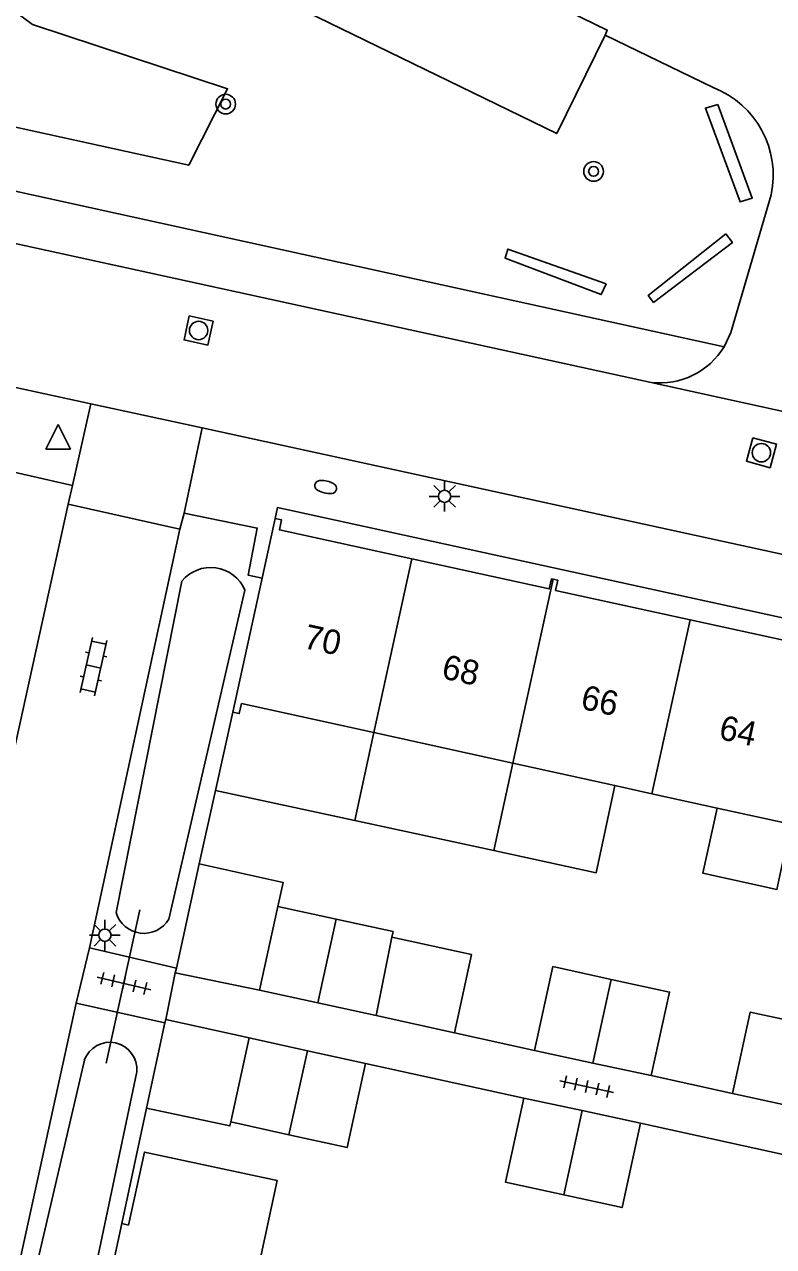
# Model space of a CAD drawing. Extents: x 130998 to 133001, y 398999 to 403002.
# Drawn here: x 131030.54 to 131061.09, y 399033.29 to 399083.14 of the extents above; entities that cross this region are included whole.
import ezdxf

# ---------------------------------------------------------------- set-up
doc = ezdxf.new("R2010")
doc.units = 0
for name, color, linetype in [('gg-afsc-erfafscheiding', 7, 'Continuous'), ('gg-afsc-muur', 7, 'Continuous'), ('gg-anno-huisnummerreeks BGT', 7, 'Continuous'), ('gg-bbg-bijgebouw', 7, 'Continuous'), ('gg-bbg-gedigitaliseerde bebouwing', 7, 'Continuous'), ('gg-bbg-gedigitaliseerde bijgebouw', 7, 'Continuous'), ('gg-bbg-hoofdgebouw', 7, 'Continuous'), ('gg-bbg-luifel en loopbrug', 7, 'Continuous'), ('gg-bbg-tussenscheiding', 7, 'Continuous'), ('gg-knt-verharding', 7, 'Continuous'), ('gg-knt-verharding nz', 7, 'Continuous'), ('gg-kntw-greppel-droge sloot', 7, 'Continuous'), ('gg-kwrk-duiker nz buis', 7, 'Continuous'), ('gt-grn-groengrens', 7, 'Continuous'), ('gt-grn-weggrens', 7, 'Continuous'), ('gt-symb-boom', 7, 'Continuous'), ('gt-symb-brandkraan', 7, 'Continuous'), ('gt-symb-klinker verharding', 7, 'Continuous'), ('gt-symb-lichtmast', 7, 'Continuous'), ('gt-symb-rioolschacht', 7, 'Continuous'), ('gt-symb-tegel verharding', 7, 'Continuous'), ('gt-symb-waterafsluiter', 7, 'Continuous')]:
    doc.layers.add(name, color=color, linetype=linetype)

# ---------------------------------------------------------------- blocks, each defined once
blk = doc.blocks.new('gt0-WAFSL')
at = {"layer": 'gt-symb-waterafsluiter'}
for p, q in [((-0.5, -0.333), (0, 0.667)), ((0, 0.667), (0.5, -0.333)), ((0.5, -0.333), (-0.5, -0.333))]:
    blk.add_line(p, q, dxfattribs=at)
blk = doc.blocks.new('gt0-RS')
at = {"layer": 'gt-symb-rioolschacht'}
blk.add_lwpolyline([(-0.5, -0.5), (0.5, -0.5), (0.5, 0.5), (-0.5, 0.5)], close=True, dxfattribs=at)
blk.add_circle((0, 0), 0.375, dxfattribs=at)
blk = doc.blocks.new('gt0-BR')
at = {"layer": 'gt-symb-brandkraan'}
for centre, radius, start, end in [((-0.244, 0), 0.206, 107.5669, 252.4331), ((0.599, -2.664), 3, 106.892, 107.5669), ((0, -0.691), 0.938, 73.108, 106.892), ((-0.599, -2.664), 3, 72.4331, 73.108), ((0.244, 0), 0.206, 287.567, 72.4331), ((0.599, 2.664), 3, 252.4331, 253.108), ((0, 0.691), 0.938, 253.108, 286.8921), ((-0.599, 2.664), 3, 286.8921, 287.567)]:
    blk.add_arc(centre, radius, start, end, dxfattribs=at)
blk = doc.blocks.new('gt0-LMAST')
at = {"layer": 'gt-symb-lichtmast'}
for p, q in [((-0.005, 0.246), (-0.005, 0.621)), ((-0.182, 0.173), (-0.447, 0.438)), ((0.172, 0.173), (0.437, 0.438)), ((-0.255, -0.004), (-0.63, -0.004)), ((-0.182, -0.181), (-0.447, -0.446)), ((-0.005, -0.254), (-0.005, -0.629)), ((0.437, -0.446), (0.172, -0.181)), ((0.245, -0.004), (0.62, -0.004))]:
    blk.add_line(p, q, dxfattribs=at)
blk.add_circle((-0.005, -0.004), 0.25, dxfattribs=at)
blk = doc.blocks.new('gt0-KL1')
at = {"layer": 'gt-symb-klinker verharding'}
for p, q in [((-1.15, 0.3), (1.15, 0.3)), ((-1, -0.3), (-1, 0.3)), ((-0.5, 0.3), (-0.5, 0.45)), ((0, -0.3), (0, 0.3)), ((0.5, 0.3), (0.5, 0.45)), ((1, -0.3), (1, 0.3)), ((-1.15, -0.3), (1.15, -0.3)), ((-0.5, -0.45), (-0.5, -0.3)), ((0.5, -0.45), (0.5, -0.3))]:
    blk.add_line(p, q, dxfattribs=at)
blk = doc.blocks.new('gt0-TEG1')
at = {"layer": 'gt-symb-tegel verharding'}
for p, q in [((-1.125, 0), (1.125, 0)), ((-0.9, -0.25), (-0.9, 0.25)), ((-0.45, -0.25), (-0.45, 0.25)), ((0, -0.25), (0, 0.25)), ((0.45, -0.25), (0.45, 0.25)), ((0.9, -0.25), (0.9, 0.25))]:
    blk.add_line(p, q, dxfattribs=at)
blk = doc.blocks.new('gt0-BOOM')
at = {"layer": 'gt-symb-boom'}
for radius in [0.4, 0.2]:
    blk.add_circle((0, 0), radius, dxfattribs=at)

msp = doc.modelspace()

# ---------------------------------------------------------------- linework, layer by layer
at = {"layer": 'gg-afsc-erfafscheiding'}
for p, q in [((131048.074, 399042.005), (131051.342, 399041.283)), ((131050.902, 399039.338), (131044.456, 399040.753)), ((131056.104, 399040.26), (131059.416, 399039.532)), ((131062.165, 399036.895), (131055.667, 399038.326))]:
    msp.add_line(p, q, dxfattribs=at)
at = {"layer": 'gg-afsc-muur'}
for p, q in [((131037.674, 399048.894), (131038.336, 399051.895)), ((131035.525, 399038.934), (131034.511, 399034.22))]:
    msp.add_line(p, q, dxfattribs=at)
at = {"layer": 'gg-bbg-bijgebouw'}
for p, q in [((131042.502, 399043.227), (131040.124, 399043.743)), ((131044.879, 399042.711), (131042.502, 399043.227)), ((131039.702, 399041.795), (131042.079, 399041.274)), ((131042.079, 399041.274), (131044.456, 399040.753)), ((131053.723, 399040.772), (131051.342, 399041.283)), ((131056.104, 399040.26), (131053.723, 399040.772)), ((131050.902, 399039.338), (131053.285, 399038.832)), ((131053.285, 399038.832), (131055.667, 399038.326))]:
    msp.add_line(p, q, dxfattribs=at)
at = {"layer": 'gg-bbg-gedigitaliseerde bebouwing'}
for p, q in [((131039.391, 399055.44), (131044.791, 399054.253)), ((131044.791, 399054.253), (131050.46, 399053.006)), ((131050.46, 399053.006), (131054.62, 399052.092)), ((131054.62, 399052.092), (131056.129, 399051.76)), ((131056.129, 399051.76), (131058.795, 399051.173)), ((131058.795, 399051.173), (131061.798, 399050.513))]:
    msp.add_line(p, q, dxfattribs=at)
msp.add_lwpolyline([(131034.781, 399034.16), (131035.436, 399037.137), (131040.85, 399035.978), (131040.119, 399032.562)], dxfattribs=at)
at = {"layer": 'gg-bbg-gedigitaliseerde bijgebouw'}
for p, q in [((131036.738, 399044.649), (131037.674, 399048.894)), ((131040.872, 399047.16), (131043.249, 399046.64)), ((131045.527, 399045.905), (131044.879, 399042.711)), ((131036.695, 399044.456), (131036.738, 399044.649)), ((131036.695, 399044.456), (131040.124, 399043.743)), ((131038.952, 399038.368), (131039.702, 399041.795)), ((131059.416, 399039.532), (131062.59, 399038.835)), ((131041.329, 399037.848), (131038.952, 399038.368))]:
    msp.add_line(p, q, dxfattribs=at)
for points in [[(131037.674, 399048.894), (131041.088, 399048.143), (131040.872, 399047.16)], [(131043.249, 399046.64), (131045.573, 399046.132), (131045.527, 399045.905)], [(131054.47, 399044.185), (131052.091, 399044.705), (131051.342, 399041.283)], [(131054.47, 399044.185), (131056.848, 399043.665), (131056.104, 399040.26)], [(131063.317, 399042.164), (131060.137, 399042.854), (131059.416, 399039.532)], [(131044.456, 399040.753), (131043.707, 399037.328), (131041.329, 399037.848)], [(131050.902, 399039.338), (131050.154, 399035.916), (131052.533, 399035.396)], [(131055.667, 399038.326), (131054.912, 399034.876), (131052.533, 399035.396)]]:
    msp.add_lwpolyline(points, dxfattribs=at)
at = {"layer": 'gg-bbg-hoofdgebouw'}
for p, q in [((131040.23, 399060.551), (131040.761, 399062.99)), ((131039.041, 399055.09), (131040.23, 399060.551)), ((131034.511, 399034.22), (131033.525, 399029.646)), ((131034.781, 399034.16), (131034.511, 399034.22))]:
    msp.add_line(p, q, dxfattribs=at)
for points in [[(131040.761, 399062.99), (131041.031, 399062.931), (131040.941, 399062.52), (131046.342, 399061.338)], [(131046.342, 399061.338), (131051.944, 399060.112), (131052.034, 399060.523), (131052.102, 399060.508)], [(131057.682, 399058.856), (131052.198, 399060.056), (131052.288, 399060.467), (131052.102, 399060.508)], [(131057.682, 399058.856), (131063.178, 399057.653), (131063.268, 399058.064), (131063.442, 399058.026)], [(131039.391, 399055.44), (131039.301, 399055.03), (131039.041, 399055.09)]]:
    msp.add_lwpolyline(points, dxfattribs=at)
at = {"layer": 'gg-bbg-luifel en loopbrug'}
for p, q in [((131038.336, 399051.895), (131039.041, 399055.09)), ((131044.791, 399054.253), (131044.015, 399050.666)), ((131050.46, 399053.006), (131049.688, 399049.438)), ((131038.336, 399051.895), (131044.015, 399050.666)), ((131044.015, 399050.666), (131049.688, 399049.438)), ((131036.273, 399042.409), (131035.525, 399038.934)), ((131036.302, 399042.543), (131036.273, 399042.409)), ((131036.302, 399042.543), (131039.702, 399041.795)), ((131044.879, 399042.711), (131048.074, 399042.005))]:
    msp.add_line(p, q, dxfattribs=at)
for points in [[(131049.688, 399049.438), (131053.851, 399048.537), (131054.62, 399052.092)], [(131061.798, 399050.513), (131061.222, 399047.85), (131058.21, 399048.512), (131058.795, 399051.173)], [(131045.527, 399045.905), (131048.768, 399045.202), (131048.074, 399042.005)], [(131038.952, 399038.368), (131038.918, 399038.208), (131035.525, 399038.934)]]:
    msp.add_lwpolyline(points, dxfattribs=at)
at = {"layer": 'gg-bbg-tussenscheiding'}
for p, q in [((131046.342, 399061.338), (131044.791, 399054.253)), ((131052.102, 399060.508), (131050.46, 399053.006)), ((131057.682, 399058.856), (131056.129, 399051.76)), ((131040.124, 399043.743), (131040.872, 399047.16)), ((131043.249, 399046.64), (131042.502, 399043.227)), ((131054.47, 399044.185), (131053.723, 399040.772)), ((131041.329, 399037.848), (131042.079, 399041.274)), ((131052.533, 399035.396), (131053.285, 399038.832))]:
    msp.add_line(p, q, dxfattribs=at)
at = {"layer": 'gg-knt-verharding'}
for p, q in [((131054.218, 399082.707), (131058.63, 399080.563)), ((131056.099, 399068.536), (131005.691, 399079.564)), ((131033.255, 399067.67), (131037.795, 399066.692)), ((131037.795, 399066.692), (131089.427, 399055.417)), ((131018.332, 399000), (131032.328, 399063.578)), ((131032.328, 399063.578), (131036.886, 399062.546)), ((131037.057, 399063.2), (131036.886, 399062.546)), ((131033.192, 399045.476), (131036.886, 399062.546)), ((131032.649, 399043.215), (131033.192, 399045.476)), ((131036.738, 399044.649), (131033.192, 399045.476)), ((131028.142, 399022.596), (131032.649, 399043.215)), ((131032.649, 399043.215), (131036.273, 399042.409))]:
    msp.add_line(p, q, dxfattribs=at)
for points in [[(131022.511, 399098.397), (131020.472, 399094.157), (131052.245, 399078.688), (131054.218, 399082.707)], [(131000, 399082.945), (131010.789, 399080.599), (131059.069, 399069.995)], [(131060.99, 399076.194), (131059.343, 399070.578), (131059.069, 399069.995)], [(131004.446, 399074.018), (131027.925, 399068.818), (131033.255, 399067.67)], [(131074.781, 399055.54), (131074.892, 399055.996), (131040.858, 399063.429), (131040.761, 399062.99)], [(131040.23, 399060.551), (131039.661, 399060.678), (131040.035, 399062.595), (131037.057, 399063.2)]]:
    msp.add_lwpolyline(points, dxfattribs=at)
for centre, radius, start, end in [((131057.243, 399076.992), 3.831, 347.977, 68.7761), ((131056.446, 399071.582), 3.066, 263.4984, 328.8264)]:
    msp.add_arc(centre, radius, start, end, dxfattribs=at)
at = {"layer": 'gg-knt-verharding nz'}
msp.add_lwpolyline([(131054.218, 399082.707), (131054.304, 399082.906), (131022.511, 399098.397)], dxfattribs=at)
at = {"layer": 'gg-kntw-greppel-droge sloot'}
for p, q in [((131034.278, 399046.911), (131036.96, 399060.436)), ((131039.533, 399060.067), (131036.432, 399046.643)), ((131032.986, 399040.886), (131028.712, 399022.479)), ((131032.897, 399029.784), (131035.121, 399040.414))]:
    msp.add_line(p, q, dxfattribs=at)
msp.add_lwpolyline([(131014.995, 399090.515), (131025.734, 399086.957), (131030.877, 399083.141), (131038.828, 399080.519), (131037.245, 399077.399), (131017.529, 399081.719)], dxfattribs=at)
for centre, radius, start, end in [((131038.133, 399059.461), 1.525, 23.4114, 140.2661), ((131035.413, 399047.246), 1.184, 196.4327, 329.3827), ((131034.024, 399040.518), 1.102, 354.563, 160.5045)]:
    msp.add_arc(centre, radius, start, end, dxfattribs=at)
at = {"layer": 'gg-kwrk-duiker nz buis'}
msp.add_line((131035.255, 399047.017), (131033.874, 399040.763), dxfattribs=at)
at = {"layer": 'gt-grn-groengrens'}
for points in [[(131058.814, 399079.882), (131058.312, 399079.728), (131059.722, 399075.902), (131060.217, 399076.055), (131058.814, 399079.882)], [(131059.139, 399074.602), (131059.411, 399074.244), (131056.197, 399071.8), (131055.977, 399072.089), (131059.139, 399074.602)], [(131054.265, 399072.565), (131054.061, 399072.122), (131050.139, 399073.602), (131050.258, 399073.981), (131054.265, 399072.565)]]:
    msp.add_lwpolyline(points, dxfattribs=at)
at = {"layer": 'gt-grn-weggrens'}
for p, q in [((131056.099, 399068.536), (131066.131, 399066.328)), ((131032.499, 399064.333), (131033.255, 399067.67)), ((131037.057, 399063.2), (131037.795, 399066.692)), ((131029.511, 399065.01), (131032.499, 399064.333)), ((131032.328, 399063.578), (131032.499, 399064.333)), ((131036.695, 399044.456), (131036.302, 399042.543))]:
    msp.add_line(p, q, dxfattribs=at)

# ---------------------------------------------------------------- block references
at = {"layer": 'gt-symb-boom'}
for p in [(131038.75, 399079.891), (131053.748, 399077.146)]:
    msp.add_blockref('gt0-BOOM', p, dxfattribs=at)
at = {"layer": 'gt-symb-brandkraan', "rotation": 167.05981811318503}
msp.add_blockref('gt0-BR', (131042.829, 399064.271), dxfattribs=at)
at = {"layer": 'gt-symb-klinker verharding', "rotation": 77.4649766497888}
msp.add_blockref('gt0-KL1', (131033.359, 399056.947), dxfattribs=at)
at = {"layer": 'gt-symb-lichtmast'}
for p in [(131047.678, 399063.895), (131033.828, 399045.99)]:
    msp.add_blockref('gt0-LMAST', p, dxfattribs=at)
at = {"layer": 'gt-symb-rioolschacht'}
for p, rotation in [((131037.646, 399070.657), 167.6550003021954), ((131060.595, 399065.671), -105.17938404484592)]:
    msp.add_blockref('gt0-RS', p, dxfattribs=dict(at, rotation=rotation))
at = {"layer": 'gt-symb-tegel verharding'}
for p, rotation in [((131034.596, 399044.019), -13.480126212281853), ((131053.468, 399039.809), -12.298855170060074)]:
    msp.add_blockref('gt0-TEG1', p, dxfattribs=dict(at, rotation=rotation))
at = {"layer": 'gt-symb-waterafsluiter'}
msp.add_blockref('gt0-WAFSL', (131031.919, 399066.154), dxfattribs=at)

# ---------------------------------------------------------------- texts
at = {"layer": 'gg-anno-huisnummerreeks BGT'}
for s, p in [('70', (131041.874, 399057.711)), ('68', (131047.508, 399056.478)), ('66', (131053.178, 399055.236)), ('64', (131058.813, 399054.003))]:
    msp.add_text(s, height=1, rotation=347.6, dxfattribs=at).set_placement(p)

doc.saveas('drawing.dxf')
